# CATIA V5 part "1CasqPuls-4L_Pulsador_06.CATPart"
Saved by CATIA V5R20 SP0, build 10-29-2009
Part number: 1CasqPuls-4L_Pulsador_06
Revision: ANY
Definition: UNKNOWN
Nomenclature: 1CasqPuls-4L_Pulsador_06
Source: Unknown
Bounding box of the stored display mesh (mm): x -5.8 to 5.8, y 0 to 15.3, z -5.8 to 5.8
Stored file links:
  C:\Users\Utente\Desktop\IO LAVORO\3D X SITO CF\CUMSA\3D files AE\AE 041620\1CasqPuls-4L_Pulsador_06.CATPart
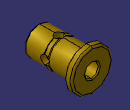
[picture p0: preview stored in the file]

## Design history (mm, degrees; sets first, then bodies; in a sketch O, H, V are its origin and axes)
Body1 "MatrizC1" (main body)
  Solid1: solid without history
